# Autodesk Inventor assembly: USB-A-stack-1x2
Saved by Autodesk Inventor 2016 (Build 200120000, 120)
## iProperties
Created: 2018-05
Part Number: USB-A-stack-1x2
Document SubType Name: Assembly
Designer: Administrator
Title: USB-A-stack-1x2 v23
Author: Administrator
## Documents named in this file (4)
- c:\worker\convert-fusion-mar-2018\tmp\job-1\16\output\files\8c58ff39-88bb-4352-afd9-60265520bae5\USB-A-stack-1x2 v23_1.iam
- c:\worker\convert-fusion-mar-2018\tmp\job-1\16\output\files\8c58ff39-88bb-4352-afd9-60265520bae5\shell_1.iam
- c:\worker\convert-fusion-mar-2018\tmp\job-1\16\output\files\8c58ff39-88bb-4352-afd9-60265520bae5\Component4_1.iam
- c:\worker\convert-fusion-mar-2018\tmp\job-1\16\output\files\8c58ff39-88bb-4352-afd9-60265520bae5\leads_2.iam
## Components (3 placed, 3 different names)
1. shell:1 [sub-assembly]
2. Component4:1 [sub-assembly]
3. leads:1 [sub-assembly]
